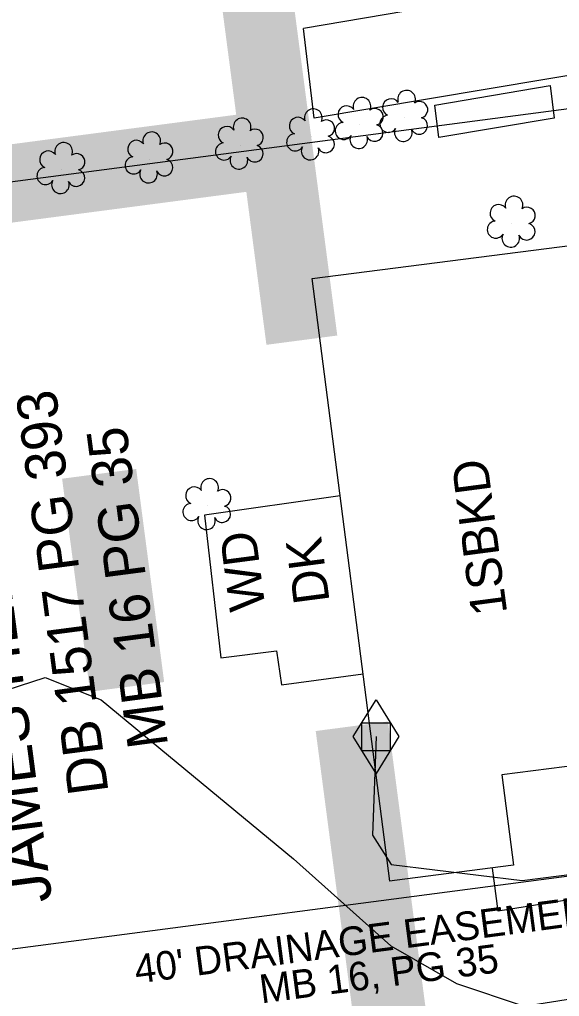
# Model space of a CAD drawing. Extents: x 2364404 to 2371833, y 798876 to 809754.
# Drawn here: x 2368362 to 2368422.3, y 806930.7 to 807039.8 of the extents above; entities that cross this region are included whole.
import ezdxf

# ---------------------------------------------------------------- set-up
doc = ezdxf.new("R2010")
doc.units = 0
for name, color, linetype in [('Exist Building', 7, 'Continuous'), ('Exist Building Text', 7, 'Continuous'), ('Exist Horizontal Baseline Alignment Station Label', 7, 'Continuous'), ('Exist Other Culture Area Outline', 7, 'Continuous'), ('Exist Other Culture Area Outline Text', 7, 'Continuous'), ('Exist Property Deed Book Text', 7, 'Continuous'), ('Exist Property Line', 7, 'Continuous'), ('Exist Property Owner Text', 7, 'Continuous'), ('Exist Right of Way Easement Line', 7, 'Continuous'), ('Exist Right of Way Easement Line Text', 7, 'Continuous'), ('Exist Roads EOP Other', 7, 'Continuous'), ('Exist Utilities Gas Meter CELL', 7, 'Continuous'), ('Exist Utilities Gas UG Line SUE LOS B', 7, 'Continuous'), ('Exist Vegetation Hedge Row', 7, 'Continuous'), ('Exist Vegetation Shrub CELL', 7, 'Continuous'), ('Exist Vegetation Woods Line', 7, 'Continuous')]:
    doc.layers.add(name, color=color, linetype=linetype)

msp = doc.modelspace()

# ---------------------------------------------------------------- linework, layer by layer
at = {"layer": 'Exist Building'}
msp.add_lwpolyline([(2368425.53, 807014.81), (2368429.96, 806980.41), (2368434.57, 806981), (2368436, 806969.91), (2368431.89, 806969.38), (2368433.4, 806957.68), (2368415.91, 806955.42), (2368417.21, 806945.33), (2368403.91, 806943.61), (2368403.39, 806943.54), (2368394.71, 807010.84)], close=True, dxfattribs=at)
at = {"layer": 'Exist Other Culture Area Outline'}
msp.add_lwpolyline([(2368397.84, 806986.58), (2368382.68, 806984.42), (2368384.53, 806968.49), (2368390.74, 806969.29), (2368391.29, 806965.47), (2368400.4, 806966.7)], dxfattribs=at)
at = {"layer": 'Exist Property Line'}
msp.add_line((2368306.01, 807014.42), (2368471.14, 807036.11), dxfattribs=at)
at = {"layer": 'Exist Right of Way Easement Line'}
msp.add_line((2368317.02, 806930.19), (2368482.09, 806951.87), dxfattribs=at)
at = {"layer": 'Exist Roads EOP Other'}
for points in [[(2368483.47, 807055.5), (2368471.47, 807051.42), (2368459.35, 807049.64), (2368443.98, 807047.15), (2368431.82, 807045.24), (2368428.61, 807044.71), (2368418.8, 807043.04), (2368393.77, 807038.77)], [(2368484.84, 807042.27), (2368478.86, 807041.92), (2368472.79, 807041.75), (2368462.27, 807040.03), (2368447.66, 807037.55), (2368433.79, 807035.27), (2368394.96, 807028.78), (2368393.77, 807038.77)], [(2368495.51, 806965.25), (2368491.99, 806966.01), (2368488.36, 806965.74), (2368482.76, 806965.01), (2368478.3, 806963.84), (2368473.64, 806962.32), (2368460.73, 806954.49), (2368456.12, 806951.69), (2368448.94, 806947.72), (2368444.73, 806945.84), (2368440.85, 806944.57), (2368432.43, 806942.91), (2368415.49, 806940.2), (2368414.86, 806945.02)]]:
    msp.add_lwpolyline(points, dxfattribs=at)
at = {"layer": 'Exist Utilities Gas Meter CELL'}
msp.add_line((2368401.85, 806959.7), (2368401.85, 806959.7), dxfattribs=at)
for points in [[(2368399.31, 806959.7), (2368401.85, 806963.81), (2368404.39, 806959.7), (2368401.85, 806955.59), (2368399.31, 806959.7)], [(2368400.28, 806961.24), (2368403.43, 806961.24), (2368403.43, 806958.12), (2368400.28, 806958.12), (2368400.28, 806961.24)]]:
    msp.add_lwpolyline(points, dxfattribs=at)
at = {"layer": 'Exist Utilities Gas UG Line SUE LOS B'}
msp.add_lwpolyline([(2368401.85, 806959.7), (2368401.46, 806948.68), (2368403.53, 806945.42), (2368418.17, 806943.63), (2368453.54, 806948.15), (2368466.19, 806949.36), (2368497.18, 806951.81), (2368498, 806951.99), (2368522.59, 806953.22), (2368522.83, 806953.25)], dxfattribs=at)
at = {"layer": 'Exist Vegetation Hedge Row'}
msp.add_lwpolyline([(2368421.73, 807028.75), (2368408.87, 807026.59), (2368408.4, 807030.21), (2368421.3, 807032.4), (2368421.73, 807028.75)], dxfattribs=at)
at = {"layer": 'Exist Vegetation Shrub CELL'}
for p, q in [((2368405.03, 807028.84), (2368405.03, 807028.84)), ((2368400.05, 807028.05), (2368400.05, 807028.05)), ((2368394.62, 807026.77), (2368394.62, 807026.77)), ((2368386.67, 807025.74), (2368386.67, 807025.74)), ((2368376.58, 807024.19), (2368376.58, 807024.19)), ((2368366.74, 807023.01), (2368366.74, 807023.01)), ((2368417.03, 807017.02), (2368417.03, 807017.02)), ((2368383.04, 806985.48), (2368383.04, 806985.48))]:
    msp.add_line(p, q, dxfattribs=at)
for centre, radius, start, end in [((2368405.26, 807030.88), 0.99, 334.8391, 200.4717), ((2368400.28, 807030.09), 0.99, 334.8391, 200.4717), ((2368403.55, 807029.96), 0.968, 35.8908, 245.4216), ((2368394.85, 807028.81), 0.99, 334.8391, 200.4717), ((2368398.57, 807029.17), 0.968, 35.8908, 245.4216), ((2368401.72, 807028.91), 0.929, 284.4567, 126.0861), ((2368406.7, 807029.7), 0.929, 284.4567, 126.0861), ((2368386.9, 807027.78), 0.99, 334.8391, 200.4717), ((2368393.14, 807027.89), 0.968, 35.8908, 245.4216), ((2368396.29, 807027.64), 0.929, 284.4567, 126.0861), ((2368403.23, 807028.13), 0.955, 95.1099, 327.9534), ((2368406.67, 807027.91), 0.937, 204.9913, 73.4601), ((2368385.19, 807026.87), 0.968, 35.8908, 245.4216), ((2368388.34, 807026.61), 0.929, 284.4567, 126.0861), ((2368398.25, 807027.34), 0.955, 95.1099, 327.9534), ((2368401.69, 807027.12), 0.937, 204.9913, 73.4601), ((2368404.9, 807027.15), 0.984, 151.2797, 21.387), ((2368376.8, 807026.23), 0.99, 334.8391, 200.4717), ((2368392.82, 807026.06), 0.955, 95.1099, 327.9534), ((2368396.26, 807025.84), 0.937, 204.9913, 73.4601), ((2368399.92, 807026.36), 0.984, 151.2797, 21.387), ((2368366.97, 807025.05), 0.99, 334.8391, 200.4717), ((2368375.09, 807025.32), 0.968, 35.8908, 245.4216), ((2368378.25, 807025.06), 0.929, 284.4567, 126.0861), ((2368384.87, 807025.04), 0.955, 95.1099, 327.9534), ((2368388.31, 807024.81), 0.937, 204.9913, 73.4601), ((2368394.49, 807025.08), 0.984, 151.2797, 21.387), ((2368365.26, 807024.13), 0.968, 35.8908, 245.4216), ((2368368.41, 807023.88), 0.929, 284.4567, 126.0861), ((2368374.78, 807023.49), 0.955, 95.1099, 327.9534), ((2368378.21, 807023.26), 0.937, 204.9913, 73.4601), ((2368386.54, 807024.06), 0.984, 151.2797, 21.387), ((2368364.94, 807022.3), 0.955, 95.1099, 327.9534), ((2368368.38, 807022.08), 0.937, 204.9913, 73.4601), ((2368376.45, 807022.51), 0.984, 151.2797, 21.387), ((2368366.61, 807021.32), 0.984, 151.2797, 21.387), ((2368417.26, 807019.06), 0.99, 334.8391, 200.4717), ((2368415.55, 807018.15), 0.968, 35.8908, 245.4216), ((2368418.7, 807017.89), 0.929, 284.4567, 126.0861), ((2368415.23, 807016.32), 0.955, 95.1099, 327.9534), ((2368418.67, 807016.09), 0.937, 204.9913, 73.4601), ((2368416.9, 807015.34), 0.984, 151.2797, 21.387), ((2368383.27, 806987.52), 0.99, 334.8391, 200.4717), ((2368381.56, 806986.61), 0.968, 35.8908, 245.4216), ((2368384.72, 806986.35), 0.929, 284.4567, 126.0861), ((2368381.24, 806984.78), 0.955, 95.1099, 327.9534), ((2368384.68, 806984.55), 0.937, 204.9913, 73.4601), ((2368382.92, 806983.8), 0.984, 151.2797, 21.387)]:
    msp.add_arc(centre, radius, start, end, dxfattribs=at)
at = {"layer": 'Exist Vegetation Woods Line'}
msp.add_lwpolyline([(2368359.15, 806964.43), (2368364.89, 806966.3), (2368371.14, 806963.81), (2368392.64, 806946.04), (2368403.49, 806936.32), (2368410.84, 806932.13), (2368418.4, 806929.6), (2368430.84, 806931.58), (2368468.71, 806937.54), (2368471.4, 806943.01), (2368470.84, 806947.58), (2368470.63, 806951.87), (2368472.01, 806954.87), (2368473.86, 806957.5), (2368476, 806959.79), (2368478.29, 806960.63), (2368481.05, 806960.93), (2368483.7, 806960.35), (2368486.49, 806958.78), (2368487.57, 806956.58), (2368489.43, 806954.43)], dxfattribs=at)

# ---------------------------------------------------------------- texts
at = {"layer": 'Exist Building Text'}
msp.add_text('1SBKD', height=4, rotation=97.4798, dxfattribs=at).set_placement((2368416.51, 806973.5))
at = {"layer": 'Exist Horizontal Baseline Alignment Station Label'}
msp.add_text('BL-111', height=73.5, rotation=97.4798, dxfattribs=at).set_placement((2368418.41, 806845.42))
at = {"layer": 'Exist Other Culture Area Outline Text'}
for s, p in [('WD', (2368389.51, 806974.02)), (' DK', (2368396.87, 806973.31))]:
    msp.add_text(s, height=4, rotation=97.4798, dxfattribs=at).set_placement(p)
at = {"layer": 'Exist Property Deed Book Text'}
for s, p in [('DB 1517 PG 393', (2368371.99, 806953.5)), ('MB 16 PG 35', (2368378.64, 806958.7))]:
    msp.add_text(s, height=4.5, rotation=97.4798, dxfattribs=at).set_placement(p)
at = {"layer": 'Exist Property Owner Text'}
msp.add_text('JAMES HENRY ROSS', height=5, rotation=97.4798, dxfattribs=at).set_placement((2368365.7, 806941.38))
at = {"layer": 'Exist Right of Way Easement Line Text'}
for s, p in [("40' DRAINAGE EASEMENT", (2368375.09, 806932.11)), ('MB 16, PG 35', (2368389.05, 806929.9))]:
    msp.add_text(s, height=3.2, rotation=7.4817, dxfattribs=at).set_placement(p)

doc.saveas('drawing.dxf')
